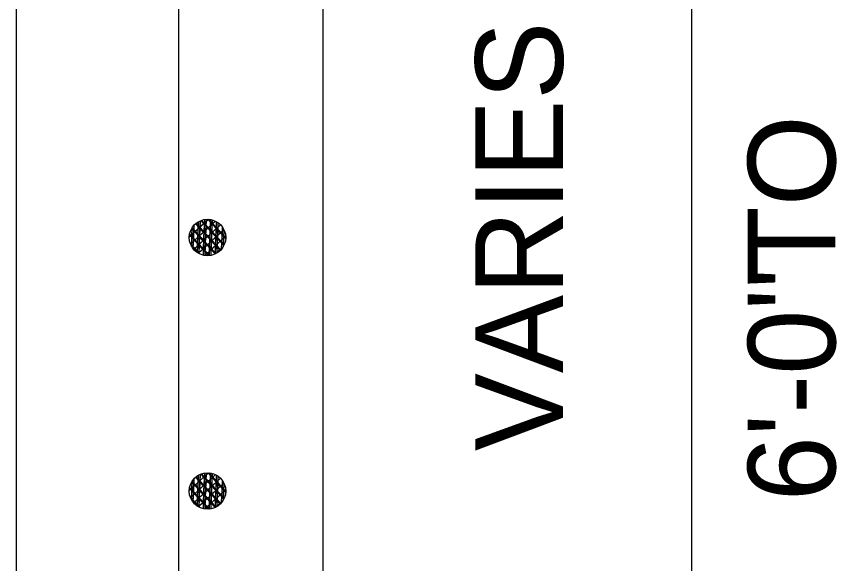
# Model space of a CAD drawing. Extents: x 1.8 to 9.1, y -6 to 4.
# Drawn here: x 4.889 to 5.451, y -2.422 to -2.048 of the extents above; entities that cross this region are included whole.
import ezdxf

# ---------------------------------------------------------------- set-up
doc = ezdxf.new("R2010")
doc.units = 0
for name, color, linetype in [('DETL-DIMS', 7, 'Continuous'), ('DETL-LINE', 7, 'Continuous'), ('DETL-NOTE', 7, 'Continuous')]:
    doc.layers.add(name, color=color, linetype=linetype)

msp = doc.modelspace()

# ---------------------------------------------------------------- linework, layer by layer
at = {"layer": 'DETL-DIMS'}
msp.add_line((5.35142, -3.23438), (5.35142, -1.12489), dxfattribs=at)
at = {"layer": 'DETL-LINE'}
for p, q in [((5.0988, -3.47273), (5.0988, -0.16697)), ((4.88852, -3.23438), (4.88852, -0.412)), ((4.99979, -3.35446), (4.99979, -1.31607)), ((5.01842, -2.18807), (5.00872, -2.19707)), ((5.02122, -2.19109), (5.01151, -2.20009)), ((5.0128, -2.20249), (5.01331, -2.18924)), ((5.02216, -2.20135), (5.0132, -2.19164)), ((5.02251, -2.20092), (5.01351, -2.19121)), ((5.01398, -2.20253), (5.01449, -2.18928)), ((5.02428, -2.1883), (5.01453, -2.1973)), ((5.02522, -2.19856), (5.01622, -2.18885)), ((5.02554, -2.19813), (5.0165, -2.18842)), ((5.01693, -2.20265), (5.01744, -2.1894)), ((5.02703, -2.19133), (5.01732, -2.20033)), ((5.01811, -2.20269), (5.01862, -2.18944)), ((5.02833, -2.20115), (5.01933, -2.19145)), ((5.02106, -2.20281), (5.02157, -2.18956)), ((5.03104, -2.1988), (5.02208, -2.18909)), ((5.02224, -2.20284), (5.02275, -2.1896)), ((5.03136, -2.19836), (5.02236, -2.18866)), ((5.02519, -2.20296), (5.0257, -2.18972)), ((5.02632, -2.203), (5.02688, -2.1898)), ((5.01614, -2.20693), (5.00714, -2.19722)), ((5.01642, -2.20654), (5.00746, -2.19683)), ((5.01819, -2.19392), (5.00848, -2.20288)), ((5.0097, -2.2065), (5.01021, -2.19325)), ((5.01913, -2.20418), (5.01017, -2.19443)), ((5.01949, -2.20375), (5.01048, -2.19404)), ((5.02102, -2.19691), (5.01127, -2.20595)), ((5.01265, -2.20662), (5.01316, -2.19337)), ((5.02196, -2.20717), (5.01296, -2.19746)), ((5.02228, -2.20678), (5.01328, -2.19707)), ((5.01383, -2.20666), (5.01434, -2.19341)), ((5.02405, -2.19416), (5.0143, -2.20312)), ((5.02499, -2.20442), (5.01599, -2.19467)), ((5.0253, -2.20395), (5.0163, -2.19424)), ((5.01677, -2.20678), (5.01728, -2.19353)), ((5.0268, -2.19715), (5.01709, -2.20615)), ((5.01795, -2.20681), (5.01846, -2.19357)), ((5.02802, -2.20159), (5.01901, -2.19188)), ((5.02813, -2.20701), (5.01909, -2.1973)), ((5.02986, -2.19435), (5.02015, -2.20336)), ((5.0209, -2.20693), (5.02141, -2.19369)), ((5.02208, -2.20697), (5.02259, -2.19373)), ((5.02503, -2.20709), (5.02554, -2.19384)), ((5.02617, -2.20713), (5.02668, -2.19388)), ((5.01894, -2.20996), (5.00993, -2.20029)), ((5.01925, -2.20957), (5.01025, -2.19982)), ((5.02381, -2.19994), (5.01406, -2.20898)), ((5.02475, -2.21019), (5.01579, -2.20049)), ((5.02507, -2.2098), (5.01607, -2.20005)), ((5.01662, -2.2109), (5.01713, -2.19766)), ((5.0178, -2.21094), (5.01831, -2.1977)), ((5.02778, -2.2074), (5.01882, -2.1977)), ((5.02963, -2.20017), (5.01992, -2.20917)), ((5.02074, -2.21106), (5.02125, -2.19781)), ((5.02188, -2.2111), (5.02239, -2.19785)), ((5.01842, -2.36176), (5.00872, -2.37076)), ((5.02122, -2.36478), (5.01151, -2.37378)), ((5.0128, -2.37618), (5.01331, -2.36294)), ((5.02216, -2.37504), (5.0132, -2.36533)), ((5.02251, -2.37461), (5.01351, -2.3649)), ((5.01398, -2.37622), (5.01449, -2.36298)), ((5.02428, -2.36199), (5.01453, -2.37099)), ((5.02522, -2.37225), (5.01622, -2.36254)), ((5.02554, -2.37182), (5.0165, -2.36211)), ((5.01693, -2.37634), (5.01744, -2.36309)), ((5.02703, -2.36502), (5.01732, -2.37402)), ((5.01811, -2.37638), (5.01862, -2.36313)), ((5.02802, -2.37528), (5.01901, -2.36557)), ((5.02833, -2.37485), (5.01933, -2.36514)), ((5.02106, -2.3765), (5.02157, -2.36325)), ((5.03104, -2.37249), (5.02208, -2.36278)), ((5.02224, -2.37654), (5.02275, -2.36329)), ((5.03136, -2.37206), (5.02236, -2.36235)), ((5.02519, -2.37665), (5.0257, -2.36341)), ((5.02632, -2.37669), (5.02688, -2.36349)), ((5.01614, -2.38062), (5.00714, -2.37092)), ((5.01642, -2.38023), (5.00746, -2.37052)), ((5.01819, -2.36761), (5.00848, -2.37658)), ((5.0097, -2.38019), (5.01021, -2.36695)), ((5.01913, -2.37787), (5.01017, -2.36812)), ((5.01949, -2.37744), (5.01048, -2.36773)), ((5.02102, -2.3706), (5.01127, -2.37964)), ((5.01265, -2.38031), (5.01316, -2.36706)), ((5.02196, -2.38086), (5.01296, -2.37115)), ((5.02228, -2.38047), (5.01328, -2.37076)), ((5.01383, -2.38035), (5.01434, -2.3671)), ((5.02405, -2.36785), (5.0143, -2.37681)), ((5.02499, -2.37811), (5.01599, -2.36836)), ((5.0253, -2.37764), (5.0163, -2.36793)), ((5.01662, -2.38459), (5.01713, -2.37135)), ((5.01677, -2.38047), (5.01728, -2.36722)), ((5.0268, -2.37084), (5.01709, -2.37984)), ((5.0178, -2.38463), (5.01831, -2.37139)), ((5.01795, -2.38051), (5.01846, -2.36726)), ((5.02778, -2.3811), (5.01882, -2.37139)), ((5.02813, -2.3807), (5.01909, -2.37099)), ((5.02986, -2.36805), (5.02015, -2.37705)), ((5.02074, -2.38475), (5.02125, -2.3715)), ((5.0209, -2.38062), (5.02141, -2.36738)), ((5.02188, -2.38479), (5.02239, -2.37154)), ((5.02208, -2.38066), (5.02259, -2.36742)), ((5.02503, -2.38078), (5.02554, -2.36754)), ((5.02617, -2.38082), (5.02668, -2.36757)), ((5.01894, -2.38365), (5.00993, -2.37398)), ((5.01925, -2.38326), (5.01025, -2.37351)), ((5.02381, -2.37363), (5.01406, -2.38267)), ((5.02475, -2.38389), (5.01579, -2.37418)), ((5.02507, -2.38349), (5.01607, -2.37375)), ((5.02963, -2.37386), (5.01992, -2.38286))]:
    msp.add_line(p, q, dxfattribs=at)
for points in [[(5.0154, -2.1909), (5.00699, -2.19864)], [(5.00986, -2.20237), (5.01033, -2.19046)], [(5.01001, -2.19825), (5.01033, -2.19046)], [(5.01017, -2.19412), (5.01033, -2.19046)], [(5.01937, -2.19832), (5.01123, -2.18956)], [(5.01658, -2.1953), (5.01123, -2.18956)], [(5.01379, -2.19227), (5.01123, -2.18956)], [(5.01968, -2.19789), (5.01166, -2.18921)], [(5.01689, -2.19487), (5.01166, -2.18921)], [(5.01406, -2.19184), (5.01166, -2.18921)], [(5.02011, -2.18653), (5.0117, -2.19424)], [(5.01296, -2.19836), (5.01335, -2.18807)], [(5.01312, -2.19424), (5.01335, -2.18807)], [(5.01328, -2.19011), (5.01335, -2.18807)], [(5.01414, -2.1984), (5.01457, -2.18748)], [(5.0143, -2.19428), (5.01457, -2.18748)], [(5.01445, -2.19015), (5.01457, -2.18748)], [(5.02011, -2.18653), (5.01473, -2.19145)], [(5.02239, -2.19553), (5.01489, -2.1874)], [(5.0196, -2.19251), (5.01489, -2.1874)], [(5.01681, -2.18944), (5.01489, -2.1874)], [(5.02271, -2.1951), (5.0154, -2.18716)], [(5.01992, -2.19207), (5.0154, -2.18716)], [(5.01713, -2.18905), (5.0154, -2.18716)], [(5.01709, -2.19852), (5.01756, -2.18661)], [(5.01725, -2.19439), (5.01756, -2.18661)], [(5.0174, -2.19027), (5.01756, -2.18661)], [(5.02487, -2.18775), (5.01756, -2.19447)], [(5.01827, -2.19856), (5.01874, -2.18649)], [(5.01842, -2.19443), (5.01874, -2.18649)], [(5.01858, -2.19031), (5.01874, -2.18649)], [(5.02825, -2.19573), (5.01968, -2.18649)], [(5.02542, -2.1927), (5.01968, -2.18649)], [(5.02263, -2.18968), (5.01968, -2.18649)], [(5.0198, -2.18665), (5.01968, -2.18649)], [(5.02829, -2.19019), (5.02035, -2.1975)], [(5.02857, -2.1953), (5.02039, -2.18653)], [(5.02577, -2.19227), (5.02039, -2.18653)], [(5.02294, -2.18928), (5.02039, -2.18653)], [(5.02122, -2.19868), (5.02169, -2.18673)], [(5.02137, -2.19455), (5.02169, -2.18673)], [(5.02153, -2.19042), (5.02169, -2.18673)], [(5.02239, -2.19872), (5.02283, -2.18697)], [(5.02255, -2.19459), (5.02283, -2.18697)], [(5.02271, -2.19046), (5.02283, -2.18697)], [(5.03191, -2.19895), (5.02515, -2.19168)], [(5.02534, -2.19884), (5.02574, -2.18822)], [(5.0255, -2.19471), (5.02574, -2.18822)], [(5.02566, -2.19058), (5.02574, -2.18822)], [(5.02652, -2.19887), (5.02688, -2.18897)], [(5.02668, -2.19475), (5.02688, -2.18897)], [(5.02684, -2.19062), (5.02688, -2.18897)], [(5.01237, -2.19369), (5.00699, -2.19864)], [(5.00931, -2.19648), (5.00699, -2.19864)], [(5.01335, -2.20395), (5.00714, -2.19722)], [(5.01052, -2.20092), (5.00714, -2.19722)], [(5.00773, -2.19789), (5.00714, -2.19722)], [(5.01363, -2.20351), (5.00722, -2.19656)], [(5.01084, -2.20049), (5.00722, -2.19656)], [(5.00805, -2.19746), (5.00722, -2.19656)], [(5.01516, -2.19667), (5.00785, -2.20351)], [(5.00856, -2.20505), (5.00903, -2.19321)], [(5.00856, -2.20505), (5.00887, -2.19734)], [(5.01638, -2.20115), (5.00864, -2.19278)], [(5.01355, -2.19809), (5.00864, -2.19278)], [(5.01076, -2.19506), (5.00864, -2.19278)], [(5.00868, -2.20233), (5.00907, -2.19204)], [(5.00883, -2.19821), (5.00907, -2.19204)], [(5.01666, -2.20072), (5.00891, -2.19231)], [(5.01387, -2.19766), (5.00891, -2.19231)], [(5.01104, -2.19463), (5.00891, -2.19231)], [(5.00899, -2.19408), (5.00907, -2.19204)], [(5.0097, -2.2067), (5.01005, -2.19738)], [(5.03065, -2.20446), (5.02184, -2.19487)], [(5.03088, -2.20391), (5.02212, -2.19447)], [(5.03069, -2.19357), (5.02318, -2.20053)], [(5.03187, -2.19966), (5.02483, -2.19211)], [(5.03187, -2.19966), (5.02766, -2.1951)], [(5.03191, -2.19895), (5.02798, -2.19471)], [(5.02915, -2.20678), (5.02967, -2.194)], [(5.02931, -2.20312), (5.02974, -2.19192)], [(5.02947, -2.19899), (5.02974, -2.19192)], [(5.02963, -2.19487), (5.02974, -2.19192)], [(5.03041, -2.20497), (5.03081, -2.19408)], [(5.03045, -2.20316), (5.03085, -2.19384)], [(5.03061, -2.19903), (5.03085, -2.19384)], [(5.03077, -2.1949), (5.03085, -2.19384)], [(5.01214, -2.1995), (5.00785, -2.20351)], [(5.00911, -2.20229), (5.00785, -2.20351)], [(5.00856, -2.20505), (5.00872, -2.20147)], [(5.0097, -2.2067), (5.0099, -2.20151)], [(5.01795, -2.19974), (5.01001, -2.20709)], [(5.01493, -2.20253), (5.01001, -2.20709)], [(5.01253, -2.20933), (5.013, -2.1975)], [(5.01253, -2.20933), (5.01284, -2.20163)], [(5.02086, -2.21133), (5.01308, -2.20288)], [(5.02078, -2.20277), (5.0132, -2.20976)], [(5.01367, -2.21), (5.01418, -2.19754)], [(5.01367, -2.21), (5.01402, -2.20167)], [(5.01662, -2.2111), (5.01697, -2.20178)], [(5.0266, -2.20296), (5.01764, -2.21126)], [(5.01776, -2.2113), (5.01815, -2.20182)], [(5.02526, -2.21), (5.01886, -2.20308)], [(5.0207, -2.21137), (5.0211, -2.20194)], [(5.02821, -2.20788), (5.02161, -2.20072)], [(5.02188, -2.21118), (5.02224, -2.20198)], [(5.02853, -2.20744), (5.02192, -2.20029)], [(5.03187, -2.19809), (5.02294, -2.20638)], [(5.03065, -2.20446), (5.0246, -2.19793)], [(5.02491, -2.21019), (5.02538, -2.19797)], [(5.02491, -2.21019), (5.02522, -2.2021)], [(5.03088, -2.20391), (5.02495, -2.1975)], [(5.03187, -2.19809), (5.02597, -2.20359)], [(5.02609, -2.20949), (5.02652, -2.19801)], [(5.02609, -2.20949), (5.02636, -2.20214)], [(5.02915, -2.20678), (5.02951, -2.19813)], [(5.02915, -2.20678), (5.02931, -2.20225)], [(5.03041, -2.20497), (5.03065, -2.19817)], [(5.03041, -2.20497), (5.03049, -2.20229)], [(5.01434, -2.21031), (5.00773, -2.2032)], [(5.01339, -2.20937), (5.00773, -2.2032)], [(5.0106, -2.2063), (5.00773, -2.2032)], [(5.00781, -2.20328), (5.00773, -2.2032)], [(5.01296, -2.20964), (5.00832, -2.20457)], [(5.01296, -2.20964), (5.00832, -2.20457)], [(5.01029, -2.20674), (5.00832, -2.20457)], [(5.01296, -2.20964), (5.0097, -2.20611)], [(5.0119, -2.20532), (5.01001, -2.20709)], [(5.01434, -2.21031), (5.01005, -2.20567)], [(5.02023, -2.21141), (5.01273, -2.20332)], [(5.01434, -2.21031), (5.01284, -2.2087)], [(5.01776, -2.20556), (5.0132, -2.20976)], [(5.01473, -2.20839), (5.0132, -2.20976)], [(5.02023, -2.21141), (5.01556, -2.20634)], [(5.02086, -2.21133), (5.01583, -2.20591)], [(5.02357, -2.20579), (5.01764, -2.21126)], [(5.02055, -2.20858), (5.01764, -2.21126)], [(5.02479, -2.21023), (5.01858, -2.20351)], [(5.03026, -2.20524), (5.02491, -2.21019)], [(5.02939, -2.20603), (5.02491, -2.21019)], [(5.03026, -2.20524), (5.02574, -2.20941)], [(5.03026, -2.20524), (5.0288, -2.20662)], [(5.01296, -2.20964), (5.01253, -2.20913)], [(5.02636, -2.20882), (5.02491, -2.21019)], [(5.02011, -2.36022), (5.0117, -2.36793)], [(5.02011, -2.36022), (5.01473, -2.36514)], [(5.01709, -2.37221), (5.01756, -2.3603)], [(5.01725, -2.36809), (5.01756, -2.3603)], [(5.0174, -2.36396), (5.01756, -2.3603)], [(5.01827, -2.37225), (5.01874, -2.36018)], [(5.01842, -2.36812), (5.01874, -2.36018)], [(5.01858, -2.364), (5.01874, -2.36018)], [(5.02825, -2.36942), (5.01968, -2.36018)], [(5.02542, -2.3664), (5.01968, -2.36018)], [(5.02263, -2.36337), (5.01968, -2.36018)], [(5.0198, -2.36034), (5.01968, -2.36018)], [(5.02857, -2.36899), (5.02039, -2.36022)], [(5.02577, -2.36596), (5.02039, -2.36022)], [(5.02294, -2.36298), (5.02039, -2.36022)], [(5.02122, -2.37237), (5.02169, -2.36042)], [(5.02137, -2.36824), (5.02169, -2.36042)], [(5.02153, -2.36412), (5.02169, -2.36042)], [(5.0154, -2.36459), (5.00699, -2.37233)], [(5.00868, -2.37603), (5.00907, -2.36573)], [(5.00883, -2.3719), (5.00907, -2.36573)], [(5.01666, -2.37441), (5.00891, -2.366)], [(5.01387, -2.37135), (5.00891, -2.366)], [(5.01104, -2.36832), (5.00891, -2.366)], [(5.00899, -2.36777), (5.00907, -2.36573)], [(5.00986, -2.37606), (5.01033, -2.36415)], [(5.01001, -2.37194), (5.01033, -2.36415)], [(5.01017, -2.36781), (5.01033, -2.36415)], [(5.01937, -2.37202), (5.01123, -2.36325)], [(5.01658, -2.36899), (5.01123, -2.36325)], [(5.01379, -2.36596), (5.01123, -2.36325)], [(5.01968, -2.37158), (5.01166, -2.3629)], [(5.01689, -2.36856), (5.01166, -2.3629)], [(5.01406, -2.36553), (5.01166, -2.3629)], [(5.01296, -2.37206), (5.01335, -2.36176)], [(5.01312, -2.36793), (5.01335, -2.36176)], [(5.01328, -2.3638), (5.01335, -2.36176)], [(5.01414, -2.37209), (5.01457, -2.36117)], [(5.0143, -2.36797), (5.01457, -2.36117)], [(5.01445, -2.36384), (5.01457, -2.36117)], [(5.02239, -2.36923), (5.01489, -2.36109)], [(5.0196, -2.3662), (5.01489, -2.36109)], [(5.01681, -2.36313), (5.01489, -2.36109)], [(5.02271, -2.36879), (5.0154, -2.36085)], [(5.01992, -2.36577), (5.0154, -2.36085)], [(5.01713, -2.36274), (5.0154, -2.36085)], [(5.02487, -2.36144), (5.01756, -2.36816)], [(5.02829, -2.36388), (5.02035, -2.37119)], [(5.02239, -2.37241), (5.02283, -2.36066)], [(5.02255, -2.36828), (5.02283, -2.36066)], [(5.02271, -2.36415), (5.02283, -2.36066)], [(5.03187, -2.37335), (5.02483, -2.36581)], [(5.03191, -2.37264), (5.02515, -2.36537)], [(5.02534, -2.37253), (5.02574, -2.36191)], [(5.0255, -2.3684), (5.02574, -2.36191)], [(5.02566, -2.36427), (5.02574, -2.36191)], [(5.02652, -2.37257), (5.02688, -2.36266)], [(5.02668, -2.36844), (5.02688, -2.36266)], [(5.02684, -2.36431), (5.02688, -2.36266)], [(5.02931, -2.37681), (5.02974, -2.36561)], [(5.02947, -2.37268), (5.02974, -2.36561)], [(5.02963, -2.36856), (5.02974, -2.36561)], [(5.01237, -2.36738), (5.00699, -2.37233)], [(5.00931, -2.37017), (5.00699, -2.37233)], [(5.01335, -2.37764), (5.00714, -2.37092)], [(5.01052, -2.37461), (5.00714, -2.37092)], [(5.00773, -2.37158), (5.00714, -2.37092)], [(5.01363, -2.3772), (5.00722, -2.37025)], [(5.01084, -2.37418), (5.00722, -2.37025)], [(5.00805, -2.37115), (5.00722, -2.37025)], [(5.01516, -2.37037), (5.00785, -2.3772)], [(5.00856, -2.37874), (5.00903, -2.36691)], [(5.00856, -2.37874), (5.00887, -2.37103)], [(5.01638, -2.37485), (5.00864, -2.36647)], [(5.01355, -2.37178), (5.00864, -2.36647)], [(5.01076, -2.36875), (5.00864, -2.36647)], [(5.0097, -2.38039), (5.01005, -2.37107)], [(5.01253, -2.38302), (5.013, -2.37119)], [(5.01367, -2.38369), (5.01418, -2.37123)], [(5.03065, -2.37815), (5.02184, -2.36856)], [(5.03088, -2.3776), (5.02212, -2.36816)], [(5.03069, -2.36726), (5.02318, -2.37422)], [(5.03065, -2.37815), (5.0246, -2.37162)], [(5.02491, -2.38389), (5.02538, -2.37166)], [(5.03088, -2.3776), (5.02495, -2.37119)], [(5.02609, -2.38318), (5.02652, -2.3717)], [(5.03187, -2.37335), (5.02766, -2.36879)], [(5.03191, -2.37264), (5.02798, -2.3684)], [(5.02915, -2.38047), (5.02967, -2.36769)], [(5.03041, -2.37866), (5.03081, -2.36777)], [(5.03045, -2.37685), (5.03085, -2.36754)], [(5.03061, -2.37272), (5.03085, -2.36754)], [(5.03077, -2.3686), (5.03085, -2.36754)], [(5.01434, -2.384), (5.00773, -2.37689)], [(5.01339, -2.38306), (5.00773, -2.37689)], [(5.0106, -2.38), (5.00773, -2.37689)], [(5.00781, -2.37697), (5.00773, -2.37689)], [(5.01214, -2.3732), (5.00785, -2.3772)], [(5.00911, -2.37599), (5.00785, -2.3772)], [(5.00856, -2.37874), (5.00872, -2.37516)], [(5.0097, -2.38039), (5.0099, -2.3752)], [(5.01795, -2.37343), (5.01001, -2.38078)], [(5.01493, -2.37622), (5.01001, -2.38078)], [(5.01253, -2.38302), (5.01284, -2.37532)], [(5.02023, -2.3851), (5.01273, -2.37701)], [(5.02086, -2.38503), (5.01308, -2.37658)], [(5.02078, -2.37646), (5.0132, -2.38345)], [(5.01367, -2.38369), (5.01402, -2.37536)], [(5.01662, -2.38479), (5.01697, -2.37547)], [(5.0266, -2.37665), (5.01764, -2.38495)], [(5.01776, -2.38499), (5.01815, -2.37551)], [(5.02479, -2.38393), (5.01858, -2.3772)], [(5.02526, -2.38369), (5.01886, -2.37677)], [(5.0207, -2.38507), (5.0211, -2.37563)], [(5.02821, -2.38157), (5.02161, -2.37441)], [(5.02188, -2.38487), (5.02224, -2.37567)], [(5.02853, -2.38113), (5.02192, -2.37398)], [(5.03187, -2.37178), (5.02294, -2.38007)], [(5.02491, -2.38389), (5.02522, -2.37579)], [(5.03187, -2.37178), (5.02597, -2.37728)], [(5.02609, -2.38318), (5.02636, -2.37583)], [(5.02915, -2.38047), (5.02951, -2.37182)], [(5.02915, -2.38047), (5.02931, -2.37595)], [(5.03041, -2.37866), (5.03065, -2.37186)], [(5.03041, -2.37866), (5.03049, -2.37599)], [(5.01296, -2.38334), (5.00832, -2.37827)], [(5.01296, -2.38334), (5.00832, -2.37827)], [(5.01029, -2.38043), (5.00832, -2.37827)], [(5.01296, -2.38334), (5.0097, -2.3798)], [(5.0119, -2.37901), (5.01001, -2.38078)], [(5.01434, -2.384), (5.01005, -2.37937)], [(5.01296, -2.38334), (5.01253, -2.38283)], [(5.01434, -2.384), (5.01284, -2.38239)], [(5.01776, -2.37925), (5.0132, -2.38345)], [(5.01473, -2.38208), (5.0132, -2.38345)], [(5.02023, -2.3851), (5.01556, -2.38003)], [(5.02086, -2.38503), (5.01583, -2.3796)], [(5.02357, -2.37948), (5.01764, -2.38495)], [(5.02055, -2.38227), (5.01764, -2.38495)], [(5.03026, -2.37893), (5.02491, -2.38389)], [(5.02939, -2.37972), (5.02491, -2.38389)], [(5.02636, -2.38251), (5.02491, -2.38389)], [(5.03026, -2.37893), (5.02574, -2.3831)], [(5.03026, -2.37893), (5.0288, -2.38031)]]:
    msp.add_lwpolyline(points, dxfattribs=at)
for centre in [(5.01945, -2.19896), (5.01945, -2.37265)]:
    msp.add_circle(centre, 0.01249, dxfattribs=at)

# ---------------------------------------------------------------- texts
at = {"layer": 'DETL-NOTE'}
for s, height, p in [('VARIES', 0.05998, (5.26298, -2.34533)), ('TO', 0.05998, (5.44969, -2.22655)), ('4\'-0"   6\'-0"', 0.0599803, (5.44969, -2.6062))]:
    msp.add_text(s, height=height, rotation=90, dxfattribs=at).set_placement(p)

doc.saveas('drawing.dxf')
